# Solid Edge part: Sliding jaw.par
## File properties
Title: Sliding Jaw
Author: Abhinav Rai
Template: Normal.par
Last saved by: Robert a Rhodes jr
Revision: 17
Application: Solid Edge
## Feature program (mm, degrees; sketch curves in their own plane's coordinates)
sketch used by "unnamed Protrusion 1" plane through (0, 0, 0) normal (0, -1, 0) x-axis (1, 0, 0)
  line (-34.0632, 44.45) -> (-34.0632, 0)
  line (-34.0632, 0) -> (5.6116, 0)
  line (5.6116, 0) -> (5.6116, 19.9608)
  line (-34.0632, 44.45) -> (-19.6102, 44.45)
  arc centre (-37.2382, 14.3002) radius 34.925 from (-19.6102, 44.45) to (-3.8245, 24.463) cw
  arc centre (2.2507, 26.3108) radius 6.35 from (-3.8245, 24.463) to (2.2507, 19.9608) ccw
  line (5.6116, 19.9608) -> (2.2507, 19.9608)
  dimension (linear) = 37.2382
extrude "unnamed Protrusion 1" add finite 69.7992 symmetric
sketch for "unnamed Protrusion 2" plane through (5.6116, 0, 9.9804) normal (1, 0, 0) x-axis (0, 1, 0)
extrude "unnamed Protrusion 2" add finite 65.0748 along -normal
sketch for "unnamed Cutout 1" plane through (-26.9258, -15.24, -27.8638) normal (0, -1, 0) x-axis (1, 0, 0)
extrude "unnamed Cutout 1" cut through along -normal
sketch for "unnamed Protrusion 3" plane through (5.6116, 0, -9.0696) normal (1, 0, 0) x-axis (0, 1, 0)
  arc centre (0, 26.5956) radius 23.9515 from (-23.8274, 29.0304) to (23.8274, 29.0304) cw
  line (-23.8274, 29.0304) -> (23.8274, 29.0304)
extrude "unnamed Protrusion 3" add through along -normal
sketch for "unnamed Hole 1" plane through (5.6116, 0, -0.1583) normal (1, 0, 0) x-axis (0, 1, 0)
hole "unnamed Hole 1" through
fillet "unnamed Round 1"
sketch for "unnamed Hole 2" plane through (-26.9258, 0, -38.1) normal (0, 0, -1) x-axis (0, 1, 0)
  hole centre (7.9375, 2.3876) bore radius 2.7686
hole "unnamed Hole 2" finite
sketch for "unnamed Hole 3" plane through (-26.9258, 0, -38.1) normal (0, 0, -1) x-axis (0, 1, 0)
  hole centre (-7.9375, 2.3876) bore radius 2.7686
hole "unnamed Hole 3" finite
sketch for "unnamed Hole 4" plane through (-34.0632, 0, 22.225) normal (-1, 0, 0) x-axis (0, -1, 0)
  hole centre (19.0754, 3.175) bore radius 3.175
hole "unnamed Hole 4" finite
sketch for "unnamed Hole 5" plane through (-34.0632, 0, 22.225) normal (-1, 0, 0) x-axis (0, -1, 0)
  hole centre (-19.0246, 3.175) bore radius 3.175
  dimension (linear) = 19.0246
hole "unnamed Hole 5" finite
pattern "unnamed Pattern 1" of "unnamed Hole 2", "unnamed Hole 3"
pattern "unnamed Pattern 2" of "unnamed Hole 4", "unnamed Hole 5"
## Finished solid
Body 1: solid body, 48 faces, 109 edges, 62 vertices.
  Faces by surface: plane 26, cylinder 16, torus 4, sphere 2
  Edges by curve: line 69, circle 33, intersection 7
Bounding box of the edges (mm; curved faces can reach further): 65.075 x 69.799 x 82.550, from (-59.4632, -34.8996, -38.1) to (5.6116, 34.8996, 44.45).
Cylindrical faces by radius (mm): R2.7686 x2, R3.1242 x1, R3.175 x8, R6.35 x2, R9.525 x1, R23.9515 x1, R34.925 x1
Toroidal faces (ring radius, tube radius in mm): R9.525 r3.175 x2, R31.75 r3.175 x2
Spherical faces by radius (mm): R3.175 x2
Planar faces by outward normal: +x 1, +y 4, +z 6, -x 3, -y 4, -z 7, oblique 1
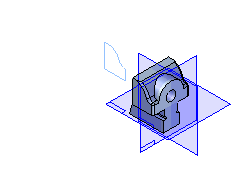
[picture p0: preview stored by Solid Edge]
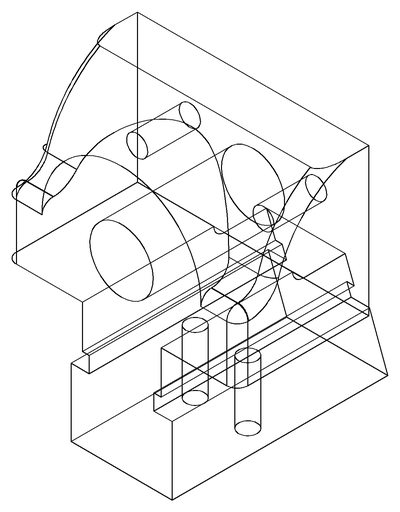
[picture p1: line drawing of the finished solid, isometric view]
